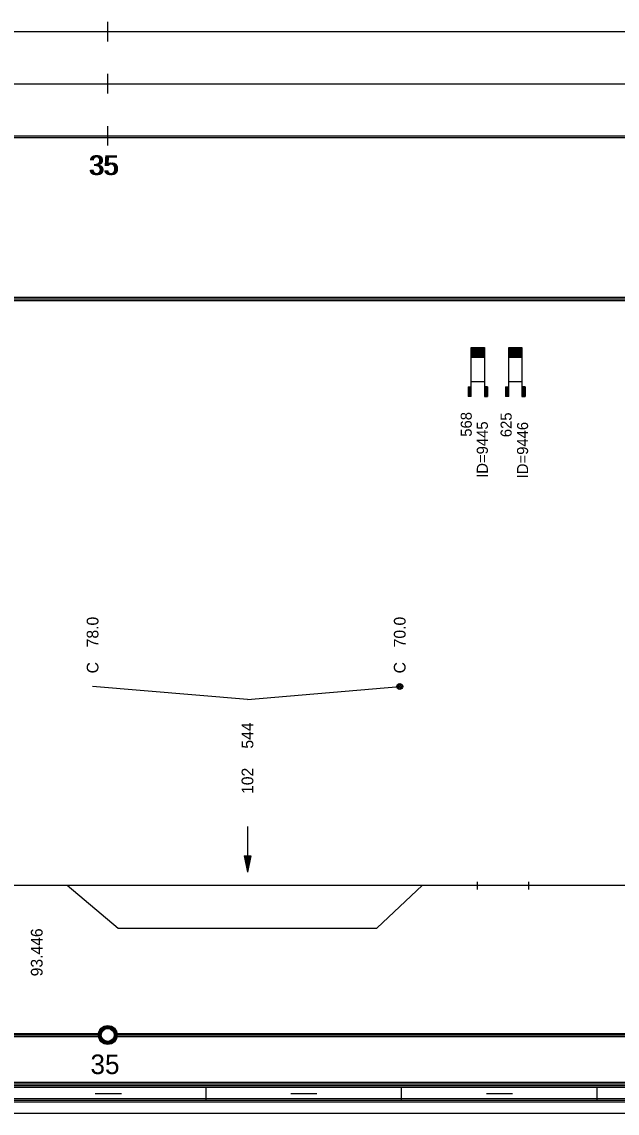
# Model space of a CAD drawing. Extents: x 2 to 10148, y 0 to 380.
# Drawn here: x 3786.7 to 3878.1, y 0 to 167.5 of the extents above; entities that cross this region are included whole.
import ezdxf

# ---------------------------------------------------------------- set-up
doc = ezdxf.new("R2010")
doc.units = 0
for name, color, linetype in [('CARA_S_OBJEKTY', 7, 'Continuous'), ('KRIV1_CARA', 7, 'Continuous'), ('KRIV1_TEXT', 7, 'Continuous'), ('OBJEKTY_TEXT', 7, 'Continuous'), ('OBJEKTY_TVAR', 7, 'Continuous'), ('RAM', 7, 'Continuous'), ('REZERVA', 7, 'Continuous'), ('RYCHL_RASTR', 7, 'Continuous'), ('RYCHL_STAN', 7, 'Continuous'), ('STAN_CARA', 7, 'Continuous'), ('STAN_TEXT', 7, 'Continuous')]:
    doc.layers.add(name, color=color, linetype=linetype)

msp = doc.modelspace()

# ---------------------------------------------------------------- linework, layer by layer
for p, q in [((3856.61, 35.51), (3856.61, 34.32)), ((3864.44, 35.51), (3864.44, 34.32))]:
    msp.add_line(p, q)
at = {"layer": 'CARA_S_OBJEKTY'}
for p, q in [((3155.54, 125.25), (4045.76, 125.25)), ((3155.54, 125), (4045.76, 125)), ((3155.54, 124.75), (4045.76, 124.75))]:
    msp.add_line(p, q, dxfattribs=at)
at = {"layer": 'KRIV1_CARA'}
for p, q in [((3155.54, 35), (4045.76, 35)), ((3793.69, 35), (3801.49, 28.38)), ((3841.21, 28.38), (3848.21, 35)), ((3801.49, 28.38), (3841.21, 28.38))]:
    msp.add_line(p, q, dxfattribs=at)
at = {"layer": 'KRIV1_TEXT'}
for p, q in [((3821.35, 63.5), (3797.59, 65.5)), ((3821.35, 63.5), (3844.71, 65.5)), ((3821.35, 44), (3821.35, 42.2)), ((3821.35, 42.2), (3821.35, 40)), ((3820.85, 39.5), (3821.35, 37)), ((3820.85, 39.5), (3821.85, 39.5)), ((3820.95, 39.5), (3821.35, 37.5)), ((3821.05, 39.5), (3821.35, 38)), ((3821.15, 39.5), (3821.35, 38.5)), ((3821.25, 39.5), (3821.35, 39)), ((3821.35, 40), (3821.35, 37)), ((3821.85, 39.5), (3821.35, 37)), ((3821.75, 39.5), (3821.35, 37.5)), ((3821.65, 39.5), (3821.35, 38)), ((3821.55, 39.5), (3821.35, 38.5)), ((3821.45, 39.5), (3821.35, 39)), ((3821.35, 39.5), (3821.35, 39.5)), ((3821.35, 39.5), (3821.35, 39.5))]:
    msp.add_line(p, q, dxfattribs=at)
for radius in [0.45, 0.3, 0.15]:
    msp.add_circle((3844.71, 65.5), radius, dxfattribs=at)
at = {"layer": 'OBJEKTY_TVAR'}
for p, q in [((3855.69, 110), (3855.69, 117.5)), ((3855.69, 117.5), (3857.69, 117.5)), ((3855.69, 117.45), (3857.69, 117.45)), ((3855.69, 117.4), (3857.69, 117.4)), ((3855.69, 117.35), (3857.69, 117.35)), ((3855.69, 117.3), (3857.69, 117.3)), ((3855.69, 117.25), (3857.69, 117.25)), ((3857.69, 117.5), (3857.69, 110)), ((3861.43, 110), (3861.43, 117.5)), ((3861.43, 117.5), (3863.43, 117.5)), ((3861.43, 117.45), (3863.43, 117.45)), ((3861.43, 117.4), (3863.43, 117.4)), ((3861.43, 117.35), (3863.43, 117.35)), ((3861.43, 117.3), (3863.43, 117.3)), ((3861.43, 117.25), (3863.43, 117.25)), ((3863.43, 117.5), (3863.43, 110)), ((3855.69, 117.2), (3857.69, 117.2)), ((3855.69, 117.15), (3857.69, 117.15)), ((3855.69, 117.1), (3857.69, 117.1)), ((3855.69, 117.05), (3857.69, 117.05)), ((3855.69, 117), (3857.69, 117)), ((3855.69, 116.95), (3857.69, 116.95)), ((3855.69, 116.9), (3857.69, 116.9)), ((3855.69, 116.85), (3857.69, 116.85)), ((3855.69, 116.8), (3857.69, 116.8)), ((3855.69, 116.75), (3857.69, 116.75)), ((3855.69, 116.7), (3857.69, 116.7)), ((3855.69, 116.65), (3857.69, 116.65)), ((3855.69, 116.6), (3857.69, 116.6)), ((3855.69, 116.55), (3857.69, 116.55)), ((3855.69, 116.5), (3857.69, 116.5)), ((3855.69, 116.45), (3857.69, 116.45)), ((3855.69, 116.4), (3857.69, 116.4)), ((3855.69, 116.35), (3857.69, 116.35)), ((3855.69, 116.3), (3857.69, 116.3)), ((3855.69, 116.25), (3857.69, 116.25)), ((3855.69, 116.2), (3857.69, 116.2)), ((3855.69, 116.15), (3857.69, 116.15)), ((3855.69, 116.1), (3857.69, 116.1)), ((3855.69, 116.05), (3857.69, 116.05)), ((3861.43, 117.2), (3863.43, 117.2)), ((3861.43, 117.15), (3863.43, 117.15)), ((3861.43, 117.1), (3863.43, 117.1)), ((3861.43, 117.05), (3863.43, 117.05)), ((3861.43, 117), (3863.43, 117)), ((3861.43, 116.95), (3863.43, 116.95)), ((3861.43, 116.9), (3863.43, 116.9)), ((3861.43, 116.85), (3863.43, 116.85)), ((3861.43, 116.8), (3863.43, 116.8)), ((3861.43, 116.75), (3863.43, 116.75)), ((3861.43, 116.7), (3863.43, 116.7)), ((3861.43, 116.65), (3863.43, 116.65)), ((3861.43, 116.6), (3863.43, 116.6)), ((3861.43, 116.55), (3863.43, 116.55)), ((3861.43, 116.5), (3863.43, 116.5)), ((3861.43, 116.45), (3863.43, 116.45)), ((3861.43, 116.4), (3863.43, 116.4)), ((3861.43, 116.35), (3863.43, 116.35)), ((3861.43, 116.3), (3863.43, 116.3)), ((3861.43, 116.25), (3863.43, 116.25)), ((3861.43, 116.2), (3863.43, 116.2)), ((3861.43, 116.15), (3863.43, 116.15)), ((3861.43, 116.1), (3863.43, 116.1)), ((3861.43, 116.05), (3863.43, 116.05)), ((3855.69, 112.31), (3857.69, 112.31)), ((3861.43, 112.31), (3863.43, 112.31)), ((3855.19, 111.5), (3855.69, 111.5)), ((3855.19, 111.5), (3855.19, 110)), ((3855.24, 111.5), (3855.24, 110)), ((3855.29, 111.5), (3855.29, 110)), ((3855.34, 111.5), (3855.34, 110)), ((3855.39, 111.5), (3855.39, 110)), ((3855.44, 111.5), (3855.44, 110)), ((3855.49, 111.5), (3855.49, 110)), ((3855.54, 111.5), (3855.54, 110)), ((3855.59, 111.5), (3855.59, 110)), ((3855.64, 111.5), (3855.64, 110)), ((3858.19, 111.5), (3857.69, 111.5)), ((3857.74, 111.5), (3857.74, 110)), ((3857.79, 111.5), (3857.79, 110)), ((3857.84, 111.5), (3857.84, 110)), ((3857.89, 111.5), (3857.89, 110)), ((3857.94, 111.5), (3857.94, 110)), ((3857.99, 111.5), (3857.99, 110)), ((3858.04, 111.5), (3858.04, 110)), ((3858.09, 111.5), (3858.09, 110)), ((3858.14, 111.5), (3858.14, 110)), ((3858.19, 111.5), (3858.19, 110)), ((3860.93, 111.5), (3861.43, 111.5)), ((3860.93, 111.5), (3860.93, 110)), ((3860.98, 111.5), (3860.98, 110)), ((3861.03, 111.5), (3861.03, 110)), ((3861.08, 111.5), (3861.08, 110)), ((3861.13, 111.5), (3861.13, 110)), ((3861.18, 111.5), (3861.18, 110)), ((3861.23, 111.5), (3861.23, 110)), ((3861.28, 111.5), (3861.28, 110)), ((3861.33, 111.5), (3861.33, 110)), ((3861.38, 111.5), (3861.38, 110)), ((3863.93, 111.5), (3863.43, 111.5)), ((3863.48, 111.5), (3863.48, 110)), ((3863.53, 111.5), (3863.53, 110)), ((3863.58, 111.5), (3863.58, 110)), ((3863.63, 111.5), (3863.63, 110)), ((3863.68, 111.5), (3863.68, 110)), ((3863.73, 111.5), (3863.73, 110)), ((3863.78, 111.5), (3863.78, 110)), ((3863.83, 111.5), (3863.83, 110)), ((3863.88, 111.5), (3863.88, 110)), ((3863.93, 111.5), (3863.93, 110)), ((3855.69, 110), (3855.19, 110)), ((3857.69, 110), (3858.19, 110)), ((3861.43, 110), (3860.93, 110)), ((3863.43, 110), (3863.93, 110))]:
    msp.add_line(p, q, dxfattribs=at)
at = {"layer": 'RAM'}
for p, q in [((3155.54, 4.75), (4045.76, 4.75)), ((3155.54, 4.5), (4045.76, 4.5)), ((3155.54, 4.25), (4045.76, 4.25)), ((3155.54, 4), (4045.76, 4)), ((3815, 2), (3815, 4)), ((3845, 2), (3845, 4)), ((3875, 2), (3875, 4)), ((3155.54, 2.25), (4045.76, 2.25)), ((3155.54, 2), (4045.76, 2)), ((3155.54, 1.75), (4045.76, 1.75)), ((3798, 3), (3802, 3)), ((3828, 3), (3832, 3)), ((3858, 3), (3862, 3)), ((3155.54, 0), (4045.76, 0))]:
    msp.add_line(p, q, dxfattribs=at)
at = {"layer": 'REZERVA'}
for radius in [1.45, 1.4, 1.35, 1.3, 1.25, 1.2, 1.15, 1.1, 1.05, 1]:
    msp.add_circle((3799.91, 12), radius, dxfattribs=at)
at = {"layer": 'RYCHL_RASTR'}
for p, q in [((3799.91, 164.5), (3799.91, 167.5)), ((3155.54, 166), (4047.1, 166)), ((3799.91, 156.5), (3799.91, 159.5)), ((3155.54, 158), (4047.25, 158)), ((3799.91, 148.5), (3799.91, 151.5)), ((3155.54, 150), (4045.76, 150)), ((3155.54, 149.75), (4045.76, 149.75))]:
    msp.add_line(p, q, dxfattribs=at)
at = {"layer": 'STAN_CARA'}
for p, q in [((3301.41, 12.25), (3798.41, 12.25)), ((3301.41, 12), (3798.41, 12)), ((3301.41, 12), (3798.41, 12)), ((3301.41, 11.75), (3798.41, 11.75)), ((3801.41, 12.25), (4045.76, 12.25)), ((3801.41, 12), (4045.76, 12)), ((3801.41, 12), (4045.76, 12)), ((3801.41, 11.75), (4045.76, 11.75))]:
    msp.add_line(p, q, dxfattribs=at)

# ---------------------------------------------------------------- texts
at = {"layer": 'KRIV1_TEXT'}
for s, p in [('78.0', (3798.49, 71.5)), ('70.0', (3845.61, 71.5)), ('C', (3798.49, 67.5)), ('C', (3845.61, 67.5)), ('544', (3822.25, 55.95)), ('102', (3822.25, 49)), ('93.446', (3789.92, 21))]:
    msp.add_text(s, height=1.8, rotation=90, dxfattribs=at).set_placement(p)
at = {"layer": 'OBJEKTY_TEXT'}
for s, p in [('568', (3855.76, 103.82)), ('625', (3861.88, 103.75)), ('ID=9445', (3858.23, 97.51)), ('ID=9446', (3864.4, 97.44))]:
    msp.add_text(s, height=1.7, rotation=90, dxfattribs=at).set_placement(p)
at = {"layer": 'RYCHL_STAN'}
for p in [(3796.97, 144), (3797.22, 144)]:
    msp.add_text('35', height=3, dxfattribs=at).set_placement(p)
at = {"layer": 'STAN_TEXT'}
msp.add_text('35', height=3, dxfattribs=at).set_placement((3797.26, 6))

doc.saveas('drawing.dxf')
